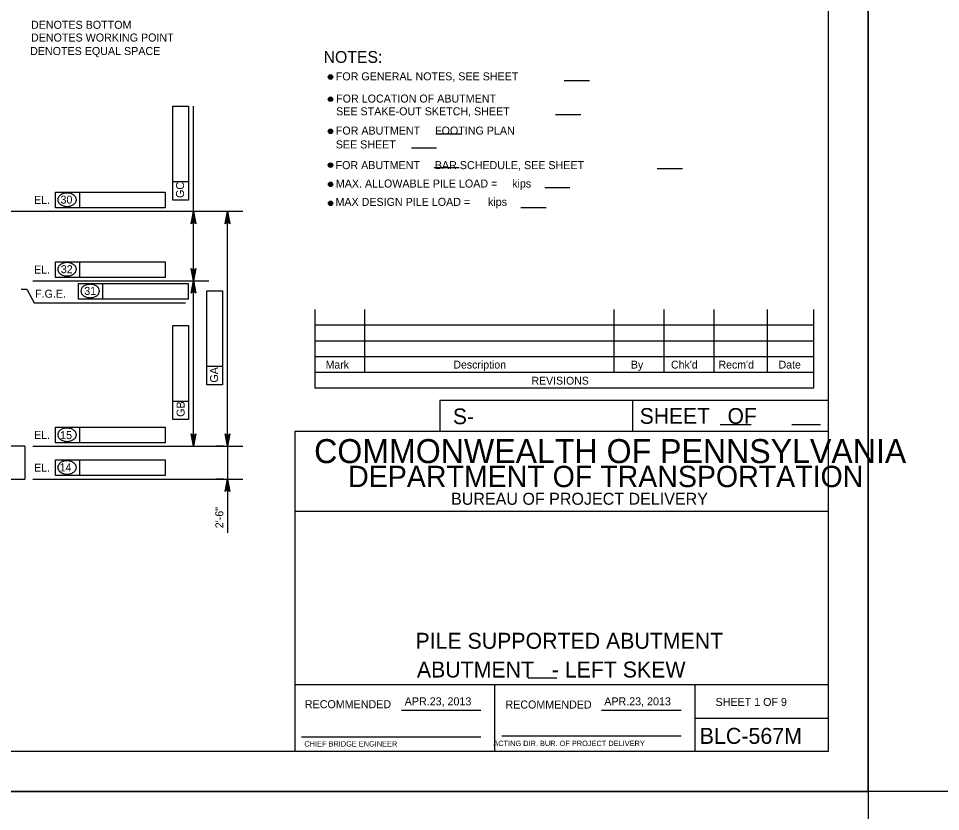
# Model space of a CAD drawing. Extents: x 638340 to 640242, y 295465 to 298435.
# Drawn here: x 638957.8 to 639303.6, y 297834 to 298131.3 of the extents above; entities that cross this region are included whole.
import ezdxf

# ---------------------------------------------------------------- set-up
doc = ezdxf.new("R2010")
doc.units = 0
for name, color, linetype in [('1', 7, 'Continuous'), ('2', 7, 'Continuous'), ('3', 7, 'Continuous'), ('4', 7, 'Continuous'), ('Level 10', 7, 'Continuous'), ('Level 3', 7, 'Continuous'), ('Level 4', 7, 'Continuous'), ('PLT-BNDY', 7, 'Continuous')]:
    doc.layers.add(name, color=color, linetype=linetype)

# ---------------------------------------------------------------- blocks, each defined once
blk = doc.blocks.new('V')
at = {"layer": '1'}
blk.add_line((0, 0), (0, 0), dxfattribs=at)

msp = doc.modelspace()

# ---------------------------------------------------------------- linework, layer by layer
at = {"layer": '2'}
for p, q in [((639261.46, 298420.46), (639261.46, 297856.46)), ((639068.92, 298022.15), (639068.92, 297992.62)), ((639087.62, 298022.15), (639087.62, 297998.53)), ((639181.13, 298022.15), (639181.13, 297998.53)), ((639199.83, 298022.15), (639199.83, 297998.53)), ((639218.53, 298022.15), (639218.53, 297998.53)), ((639238.59, 298022.15), (639238.59, 297998.53)), ((639255.94, 298022.15), (639255.94, 297992.62)), ((639255.94, 298016.24), (639068.92, 298016.24)), ((639255.94, 298010.34), (639068.92, 298010.34)), ((639255.94, 298004.43), (639068.92, 298004.43)), ((639255.94, 297998.53), (639068.92, 297998.53)), ((639255.94, 297992.62), (639068.92, 297992.62)), ((639261.46, 297988.11), (639115.78, 297988.11)), ((639115.78, 297988.11), (639115.78, 297976.46)), ((639188.09, 297988.11), (639188.09, 297976.46)), ((639261.46, 297988.11), (639261.46, 297976.46)), ((639220.95, 297979), (639232.6, 297979)), ((639247.83, 297979), (639258.56, 297979)), ((639261.46, 297976.46), (639061.46, 297976.46)), ((639061.46, 297976.46), (639061.46, 297856.46)), ((639261.46, 297946.46), (639061.46, 297946.46)), ((639261.46, 297881.46), (639061.46, 297881.46)), ((639136.46, 297856.46), (639136.46, 297881.46)), ((639211.46, 297881.46), (639211.46, 297856.46)), ((639101.42, 297871.96), (639131.19, 297871.96)), ((639176.42, 297871.96), (639206.33, 297871.96)), ((639211.46, 297868.96), (639261.46, 297868.96)), ((639063.96, 297861.96), (639131.19, 297861.96)), ((639139.08, 297862.33), (639206.33, 297862.33)), ((639261.46, 297856.46), (638475.46, 297856.46))]:
    msp.add_line(p, q, dxfattribs=at)
at = {"layer": '4'}
msp.add_line((639149.01, 297884.13), (639159.67, 297884.13), dxfattribs=at)
at = {"layer": 'Level 10'}
for p, q in [((638960.22, 297970.89), (638812.39, 297970.89)), ((638960.22, 297970.89), (638960.22, 297958.61)), ((638579.73, 297958.61), (638960.22, 297958.61))]:
    msp.add_line(p, q, dxfattribs=at)
at = {"layer": 'Level 3'}
for p, q in [((639162.48, 298108.03), (639171.93, 298108.03)), ((639015.73, 298098.38), (639021.62, 298098.38)), ((639015.73, 298069.98), (639015.73, 298098.38)), ((639021.62, 298098.38), (639021.62, 298063.14)), ((639023.45, 298032.9), (639023.45, 298098.4)), ((639159.23, 298095.32), (639168.67, 298095.32)), ((639114.31, 298088.04), (639123.76, 298088.04)), ((639105.17, 298082.77), (639114.62, 298082.77)), ((639113.66, 298075.41), (639123.11, 298075.41)), ((639197.33, 298075.02), (639206.77, 298075.02)), ((639015.73, 298063.14), (639015.73, 298069.98)), ((639021.62, 298069.98), (639015.73, 298069.98)), ((638971.69, 298066.17), (638980.84, 298066.17)), ((638971.69, 298060.27), (638971.69, 298066.17)), ((638980.84, 298060.27), (638980.84, 298066.17)), ((638980.84, 298066.17), (639012.82, 298066.17)), ((639012.82, 298066.17), (639012.82, 298060.27)), ((639155.15, 298067.89), (639164.6, 298067.89)), ((639021.62, 298063.14), (639015.73, 298063.14)), ((638910.05, 298058.99), (639041.97, 298058.99)), ((639012.82, 298060.27), (638971.69, 298060.27)), ((639020.99, 298058.99), (639027.87, 298058.99)), ((639029.89, 298058.99), (639040.63, 298058.99)), ((639035.12, 298058.99), (639040.63, 298058.99)), ((639036.21, 297970.89), (639036.21, 298058.99)), ((639146.25, 298060.45), (639155.69, 298060.45)), ((638971.69, 298040.07), (638980.84, 298040.07)), ((638971.69, 298034.18), (638971.69, 298040.07)), ((638980.84, 298034.18), (638980.84, 298040.07)), ((638980.84, 298040.07), (639012.82, 298040.07)), ((639012.82, 298040.07), (639012.82, 298034.18)), ((639012.82, 298034.18), (638971.69, 298034.18)), ((638963.21, 298032.9), (639029.21, 298032.9)), ((638980.37, 298031.94), (638989.52, 298031.94)), ((638980.37, 298026.05), (638980.37, 298031.94)), ((638989.52, 298026.05), (638989.52, 298031.94)), ((638989.52, 298031.94), (639021.5, 298031.94)), ((639018.11, 298032.9), (639027.87, 298032.9)), ((639021.5, 298031.94), (639021.5, 298026.05)), ((639023.45, 297970.89), (639023.45, 298032.9)), ((638960.98, 298029.83), (638963.75, 298024.64)), ((639028.49, 298029.17), (639034.39, 298029.17)), ((639028.49, 298000.77), (639028.49, 298029.17)), ((639034.39, 298029.17), (639034.39, 297993.94)), ((638963.75, 298024.64), (639020.44, 298024.64)), ((639021.5, 298026.05), (638980.37, 298026.05)), ((639015.73, 298016.13), (639021.62, 298016.13)), ((639015.73, 297987.72), (639015.73, 298016.13)), ((639021.62, 298016.13), (639021.62, 297980.89)), ((639028.49, 297993.94), (639028.49, 298000.77)), ((639034.39, 298000.77), (639028.49, 298000.77)), ((639034.39, 297993.94), (639028.49, 297993.94)), ((639015.73, 297980.89), (639015.73, 297987.72)), ((639021.62, 297987.72), (639015.73, 297987.72)), ((639021.62, 297980.89), (639015.73, 297980.89)), ((638971.69, 297978.06), (638980.84, 297978.06)), ((638971.69, 297972.16), (638971.69, 297978.06)), ((638980.84, 297972.16), (638980.84, 297978.06)), ((638980.84, 297978.06), (639012.82, 297978.06)), ((639012.82, 297978.06), (639012.82, 297972.16)), ((639012.82, 297972.16), (638971.69, 297972.16)), ((638963.21, 297970.89), (639041.97, 297970.89)), ((639029.89, 297970.89), (639040.63, 297970.89)), ((639034.74, 297970.89), (639031.79, 297970.89)), ((639034.65, 297970.89), (639040.63, 297970.89)), ((639035.12, 297970.89), (639040.63, 297970.89)), ((639036.21, 297970.89), (639036.21, 297958.61)), ((638971.69, 297959.89), (638971.69, 297965.78)), ((638971.69, 297965.78), (638980.84, 297965.78)), ((638980.84, 297959.89), (638980.84, 297965.78)), ((638980.84, 297965.78), (639012.82, 297965.78)), ((639012.82, 297965.78), (639012.82, 297959.89)), ((638963.21, 297958.61), (639041.97, 297958.61)), ((639012.82, 297959.89), (638971.69, 297959.89)), ((639034.74, 297958.61), (639031.79, 297958.61)), ((639036.21, 297958.61), (639036.21, 297938.44))]:
    msp.add_line(p, q, dxfattribs=at)
for points in [[(639023.45, 298058.99), (639024.32, 298054.34), (639024.07, 298054.7), (639023.76, 298054.88), (639023.45, 298054.94), (639023.13, 298054.88), (639022.82, 298054.7), (639022.58, 298054.34), (639023.45, 298058.99), (639022.82, 298054.7), (639023.13, 298054.88), (639023.45, 298058.99), (639023.45, 298054.94), (639023.76, 298054.88), (639023.45, 298058.99), (639024.07, 298054.7)], [(639036.21, 298058.99), (639037.08, 298054.34), (639036.83, 298054.7), (639036.52, 298054.88), (639036.21, 298054.94), (639035.9, 298054.88), (639035.58, 298054.7), (639035.34, 298054.34), (639036.21, 298058.99), (639035.58, 298054.7), (639035.9, 298054.88), (639036.21, 298058.99), (639036.21, 298054.94), (639036.52, 298054.88), (639036.21, 298058.99), (639036.83, 298054.7)], [(639023.45, 298032.9), (639022.58, 298037.55), (639022.82, 298037.19), (639023.13, 298037.01), (639023.45, 298036.95), (639023.76, 298037.01), (639024.07, 298037.19), (639024.32, 298037.55), (639023.45, 298032.9), (639024.07, 298037.19), (639023.76, 298037.01), (639023.45, 298032.9), (639023.45, 298036.95), (639023.13, 298037.01), (639023.45, 298032.9), (639022.82, 298037.19)], [(639023.45, 298032.9), (639024.32, 298028.25), (639024.07, 298028.6), (639023.76, 298028.79), (639023.45, 298028.84), (639023.13, 298028.79), (639022.82, 298028.6), (639022.58, 298028.25), (639023.45, 298032.9), (639022.82, 298028.6), (639023.13, 298028.79), (639023.45, 298032.9), (639023.45, 298028.84), (639023.76, 298028.79), (639023.45, 298032.9), (639024.07, 298028.6)], [(639023.45, 297970.89), (639022.58, 297975.54), (639022.82, 297975.18), (639023.13, 297974.99), (639023.45, 297974.94), (639023.76, 297974.99), (639024.07, 297975.18), (639024.32, 297975.54), (639023.45, 297970.89), (639024.07, 297975.18), (639023.76, 297974.99), (639023.45, 297970.89), (639023.45, 297974.94), (639023.13, 297974.99), (639023.45, 297970.89), (639022.82, 297975.18)], [(639036.21, 297970.89), (639035.34, 297975.54), (639035.58, 297975.18), (639035.9, 297974.99), (639036.21, 297974.94), (639036.52, 297974.99), (639036.83, 297975.18), (639037.08, 297975.54), (639036.21, 297970.89), (639036.83, 297975.18), (639036.52, 297974.99), (639036.21, 297970.89), (639036.21, 297974.94), (639035.9, 297974.99), (639036.21, 297970.89), (639035.58, 297975.18)], [(639036.21, 297958.61), (639037.08, 297953.96), (639036.83, 297954.31), (639036.52, 297954.5), (639036.21, 297954.55), (639035.9, 297954.5), (639035.58, 297954.31), (639035.34, 297953.96), (639036.21, 297958.61), (639035.58, 297954.31), (639035.9, 297954.5), (639036.21, 297958.61), (639036.21, 297954.55), (639036.52, 297954.5), (639036.21, 297958.61), (639036.83, 297954.31)]]:
    msp.add_lwpolyline(points, dxfattribs=at)
for points in [[(639022.96, 298056.05), (639023.94, 298056.05), (639023.45, 298058.99)], [(639035.72, 298056.05), (639036.7, 298056.05), (639036.21, 298058.99)], [(639022.96, 298035.84), (639023.94, 298035.84), (639023.45, 298032.9)], [(639022.96, 298029.95), (639023.94, 298029.95), (639023.45, 298032.9)], [(639022.96, 297973.83), (639023.94, 297973.83), (639023.45, 297970.89)], [(639035.72, 297973.83), (639036.7, 297973.83), (639036.21, 297970.89)], [(639035.72, 297955.66), (639036.7, 297955.66), (639036.21, 297958.61)]]:
    msp.add_lwpolyline(points, close=True, dxfattribs=at)
for centre, radius in [((639074.85, 298109.34), 0.832), ((639074.85, 298109.34), 0.624), ((639074.85, 298109.34), 0.416), ((639074.85, 298109.34), 0.208), ((639074.85, 298100.99), 0.832), ((639074.85, 298100.99), 0.624), ((639074.85, 298100.99), 0.416), ((639074.85, 298100.99), 0.208), ((639074.85, 298088.97), 0.832), ((639074.85, 298088.97), 0.624), ((639074.85, 298088.97), 0.416), ((639074.85, 298088.97), 0.208), ((639074.85, 298076.28), 0.832), ((639074.85, 298076.28), 0.624), ((639074.85, 298076.28), 0.416), ((639074.85, 298076.28), 0.208), ((639074.87, 298069.1), 0.832), ((639074.87, 298069.1), 0.624), ((639074.87, 298069.1), 0.416), ((639074.87, 298069.1), 0.208), ((639074.87, 298061.98), 0.832), ((639074.87, 298061.98), 0.624), ((639074.87, 298061.98), 0.416), ((639074.87, 298061.98), 0.208)]:
    msp.add_circle(centre, radius, dxfattribs=at)
for centre, radius, start, end in [((638975.19, 298062.86), 2.75, 125.6316, 149.9767), ((638975.72, 298062.13), 3.65, 106.5358, 125.6316), ((638976.06, 298060.97), 4.86, 90, 106.5358), ((638976.06, 298060.97), 4.86, 73.4642, 90), ((638976.4, 298062.13), 3.65, 54.3684, 73.4642), ((638976.93, 298062.86), 2.75, 30.0233, 54.3684), ((638974.39, 298063.33), 1.82, 149.9767, 180), ((638974.39, 298063.33), 1.82, 180, 210.0233), ((638975.19, 298063.79), 2.75, 210.0233, 234.3684), ((638975.72, 298064.52), 3.65, 234.3684, 253.4642), ((638976.4, 298064.52), 3.65, 286.5358, 305.6316), ((638976.93, 298063.79), 2.75, 305.6316, 329.9767), ((638977.73, 298063.33), 1.82, 0, 30.0233), ((638977.73, 298063.33), 1.82, 329.9767, 0), ((638976.06, 298065.68), 4.86, 253.4642, 270), ((638976.06, 298065.68), 4.86, 270, 286.5358), ((638974.39, 298037.23), 1.82, 149.9767, 180), ((638974.39, 298037.23), 1.82, 180, 210.0233), ((638975.19, 298036.77), 2.75, 125.6316, 149.9767), ((638975.72, 298036.03), 3.65, 106.5358, 125.6316), ((638976.06, 298034.88), 4.86, 90, 106.5358), ((638976.06, 298034.88), 4.86, 73.4642, 90), ((638976.4, 298036.03), 3.65, 54.3684, 73.4642), ((638976.93, 298036.77), 2.75, 30.0233, 54.3684), ((638977.73, 298037.23), 1.82, 0, 30.0233), ((638977.73, 298037.23), 1.82, 329.9767, 0), ((638975.19, 298037.7), 2.75, 210.0233, 234.3684), ((638975.72, 298038.43), 3.65, 234.3684, 253.4642), ((638976.06, 298039.59), 4.86, 253.4642, 270), ((638976.06, 298039.59), 4.86, 270, 286.5358), ((638976.4, 298038.43), 3.65, 286.5358, 305.6316), ((638976.93, 298037.7), 2.75, 305.6316, 329.9767), ((638983.86, 298028.64), 2.75, 125.6316, 149.9767), ((638984.39, 298027.91), 3.65, 106.5358, 125.6316), ((638984.73, 298026.75), 4.86, 90, 106.5358), ((638984.73, 298026.75), 4.86, 73.4642, 90), ((638985.08, 298027.91), 3.65, 54.3684, 73.4642), ((638985.6, 298028.64), 2.75, 30.0233, 54.3684), ((638983.06, 298029.1), 1.82, 149.9767, 180), ((638983.06, 298029.1), 1.82, 180, 210.0233), ((638983.86, 298029.57), 2.75, 210.0233, 234.3684), ((638984.39, 298030.3), 3.65, 234.3684, 253.4642), ((638984.73, 298031.46), 4.86, 253.4642, 270), ((638984.73, 298031.46), 4.86, 270, 286.5358), ((638985.08, 298030.3), 3.65, 286.5358, 305.6316), ((638985.6, 298029.57), 2.75, 305.6316, 329.9767), ((638986.41, 298029.1), 1.82, 0, 30.0233), ((638986.41, 298029.1), 1.82, 329.9767, 0), ((638974.39, 297975.22), 1.82, 149.9767, 180), ((638974.39, 297975.22), 1.82, 180, 210.0233), ((638975.19, 297974.75), 2.75, 125.6316, 149.9767), ((638975.72, 297974.02), 3.65, 106.5358, 125.6316), ((638976.06, 297972.86), 4.86, 90, 106.5358), ((638976.06, 297972.86), 4.86, 73.4642, 90), ((638976.4, 297974.02), 3.65, 54.3684, 73.4642), ((638976.93, 297974.75), 2.75, 30.0233, 54.3684), ((638977.73, 297975.22), 1.82, 0, 30.0233), ((638977.73, 297975.22), 1.82, 329.9767, 0), ((638975.19, 297975.68), 2.75, 210.0233, 234.3684), ((638975.72, 297976.42), 3.65, 234.3684, 253.4642), ((638976.06, 297977.57), 4.86, 253.4642, 270), ((638976.06, 297977.57), 4.86, 270, 286.5358), ((638976.4, 297976.42), 3.65, 286.5358, 305.6316), ((638976.93, 297975.68), 2.75, 305.6316, 329.9767), ((638975.19, 297962.47), 2.75, 125.6316, 149.9767), ((638975.72, 297961.74), 3.65, 106.5358, 125.6316), ((638976.06, 297960.58), 4.86, 90, 106.5358), ((638976.06, 297960.58), 4.86, 73.4642, 90), ((638976.4, 297961.74), 3.65, 54.3684, 73.4642), ((638976.93, 297962.47), 2.75, 30.0233, 54.3684), ((638974.39, 297962.94), 1.82, 149.9767, 180), ((638974.39, 297962.94), 1.82, 180, 210.0233), ((638975.19, 297963.4), 2.75, 210.0233, 234.3684), ((638975.72, 297964.14), 3.65, 234.3684, 253.4642), ((638976.4, 297964.14), 3.65, 286.5358, 305.6316), ((638976.93, 297963.4), 2.75, 305.6316, 329.9767), ((638977.73, 297962.94), 1.82, 0, 30.0233), ((638977.73, 297962.94), 1.82, 329.9767, 0), ((638976.06, 297965.29), 4.86, 253.4642, 270), ((638976.06, 297965.29), 4.86, 270, 286.5358)]:
    msp.add_arc(centre, radius, start, end, dxfattribs=at)
at = {"layer": 'Level 4'}
msp.add_line((638958.92, 298029.83), (638960.98, 298029.83), dxfattribs=at)
at = {"layer": 'PLT-BNDY'}
for points in [[(638435.46, 298435.46), (639276.46, 298435.46), (639276.46, 297841.46), (638435.46, 297841.46)], [(639276.46, 298435.46), (640117.46, 298435.46), (640117.46, 297841.46), (639276.46, 297841.46)], [(638435.46, 297841.46), (639276.46, 297841.46), (639276.46, 297247.46), (638435.46, 297247.46)]]:
    msp.add_lwpolyline(points, close=True, dxfattribs=at)

# ---------------------------------------------------------------- block references
at = {"layer": 'Level 3', "xscale": 0.7859001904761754, "yscale": 0.7859001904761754}
msp.add_blockref('V', (638997.32, 297965.63), dxfattribs=at)

# ---------------------------------------------------------------- texts
at = {"layer": '1'}
msp.add_text('SHEET 1 OF 9', height=3, dxfattribs=at).set_placement((639219.21, 297873.55))
at = {"layer": '2'}
for s, height, p in [('Mark', 2.952, (639073.02, 298000.03)), ('Description', 2.9523, (639120.92, 298000.03)), ('By', 2.952, (639187.49, 298000.03)), ("Chk'd", 2.952, (639202.52, 298000.03)), ("Recm'd", 2.953, (639220.33, 298000.03)), ('Date', 2.952, (639242.86, 298000.03)), ('REVISIONS', 2.952, (639150.2, 297994.01)), ('S-', 5.905, (639120.73, 297979.17)), ('SHEET   OF', 5.907, (639190.78, 297979.31)), ('COMMONWEALTH OF PENNSYLVANIA', 9, (639068.71, 297964.58)), ('DEPARTMENT OF TRANSPORTATION', 8.0002, (639081.46, 297955.58)), ('BUREAU OF PROJECT DELIVERY', 4.5, (639120.05, 297948.96)), ('APR.23, 2013', 3, (639102.67, 297873.77)), ('APR.23, 2013', 3, (639177.48, 297873.77)), ('BLC-567M', 6, (639213.27, 297859.33)), ('CHIEF BRIDGE ENGINEER', 2.0002, (639065.05, 297858.33)), ('  ACTING DIR. BUR. OF PROJECT DELIVERY', 2.0002, (639134.36, 297858.51))]:
    msp.add_text(s, height=height, dxfattribs=at).set_placement(p)
for p in [(639065.23, 297872.71), (639140.44, 297872.58)]:
    msp.add_text('RECOMMENDED', height=3, rotation=360, dxfattribs=at).set_placement(p)
at = {"layer": '3'}
msp.add_text('NOTES:', height=4.429, dxfattribs=at).set_placement((639072.25, 298114.62))
at = {"layer": '4'}
for s, p in [('PILE SUPPORTED ABUTMENT', (639106.7, 297894.99)), ('ABUTMENT   - LEFT SKEW', (639107.23, 297884.21))]:
    msp.add_text(s, height=5.9716, dxfattribs=at).set_placement(p)
at = {"layer": 'Level 3'}
for s, height, p in [('DENOTES BOTTOM', 3.0001, (638962.54, 298127.39)), ('DENOTES WORKING POINT', 3.0001, (638962.54, 298122.62)), ('DENOTES EQUAL SPACE', 3.0001, (638962.2, 298117.57)), ('FOR GENERAL NOTES, SEE SHEET    ', 3.0001, (639076.83, 298108.07)), ('FOR LOCATION OF ABUTMENT', 3.0001, (639076.95, 298099.74)), ('SEE STAKE-OUT SKETCH, SHEET    ', 3.0001, (639076.95, 298094.97)), ('FOR ABUTMENT     FOOTING PLAN', 3.0001, (639076.83, 298087.74)), ('SEE SHEET    ', 3.0001, (639076.83, 298082.55)), ('FOR ABUTMENT     BAR SCHEDULE, SEE SHEET    ', 3.0001, (639076.74, 298074.79)), ('MAX. ALLOWABLE PILE LOAD =     kips', 3.0001, (639076.84, 298067.89)), ('EL.', 3, (638963.69, 298061.75)), ('30', 3, (638973.6, 298061.86)), ('MAX DESIGN PILE LOAD =      kips', 3.0001, (639076.71, 298061.01)), ('EL.', 3, (638963.69, 298035.65)), ('32', 3, (638973.71, 298035.77)), ('31', 3, (638982.51, 298027.64)), ('F.G.E.', 3, (638964.07, 298026.58)), ('EL.', 3, (638963.69, 297973.64)), ('15', 3, (638973.47, 297973.57)), ('EL.', 3, (638963.69, 297961.36)), ('14', 3, (638973.25, 297961.48))]:
    msp.add_text(s, height=height, dxfattribs=at).set_placement(p)
for s, p in [('GC', (639019.93, 298063.97)), ('GA', (639032.69, 297994.76)), ('GB', (639020.14, 297981.94)), ('2\'-6"', (639034.67, 297940.15))]:
    msp.add_text(s, height=3, rotation=90, dxfattribs=at).set_placement(p)

doc.saveas('drawing.dxf')
